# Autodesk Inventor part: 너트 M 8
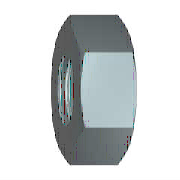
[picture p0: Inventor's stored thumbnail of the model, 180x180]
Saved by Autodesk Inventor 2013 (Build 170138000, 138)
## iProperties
IsCustomPart: 1
Created: 2012-02
Part Number: 너트 M 8
Material: 강철, 연강
Description: 6각 너트 및 6각 가는 너트
Document SubType Name: Modeling
Standard: KS B 1012
Designer: mduedu
Standards Organization: KS
Language: ko-KR
Size Designation: M 8
Categories: <MemberInstance><Categories><Category DisplayName="조임쇠" InternalName="e4da775c-781d-43d5-af7c-5136215cf5a6" Mnemonic="FSTN"><Category DisplayName="너트" InternalN
Density: 1 g/cm^3
Author: mduedu
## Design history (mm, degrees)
sketch "스케치1"
  geometry: L1 (-7.506, 0)-(-3.753, 6.5); L2 (-3.753, 6.5)-(3.753, 6.5); L3 (3.753, 6.5)-(7.506, 0); L4 (7.506, 0)-(3.753, -6.5); L5 (3.753, -6.5)-(-3.753, -6.5); L6 (-3.753, -6.5)-(-7.506, 0); 2 further points
  constraints: 12 end point, 1 coincident, 1 horizontal, 11 other
  dimensions: "d0" = 15.01111 distance of L3.end L1.start (= 1.1547 x SW)
extrude "본체" new body sketch "스케치1" distance "d1" = 5 (= KOH); taper "d2" = 0 deg
sketch "스케치2"
  geometry: L1 (0, 3.753)-(0, 7.506) reference; L2 (0, 7.506)-(5, 7.506) reference; L3 (5, 3.753)-(5, 7.506) reference; L4 (-1, 0)-(6, 0) reference; L5 (0.581, 7.506)-(0, 6.5); L6 (4.419, 7.506)-(5, 6.5)
  constraints: 4 end point, 4 point on line
  dimensions: "d3" = 30 deg angle of L1 L5 (= ANG1); "d4" = 30 deg angle of L3 L6 (= ANG2); "d5" = 13 diameter of L5.end L4 (= SW0); "d6" = 13 diameter of L6.end L4 (= SW01)
revolve "모따기1" sketch "스케치2" stored, may be unused: angle "d7" = 90 deg
sketch "스케치3"
  geometry: A1 r 6.5 centre (0, 0) between (-3.25, -5.629) and (3.25, -5.629) reference; 1 further point
  constraints: 1 coincident
hole "스레드" sketch "스케치3" at (0, 0) diameter "d25" = 6.647; stored, may be unused: countersink angle "d29" = 82 deg, drill point angle "d31" = 118 deg; dims "d26" = 6, "d27" = 4, "d28" = 2, "d30" = 8
workaxis "Work Axis1"
workplane "Work Plane1"
body "Solid1"
chamfer "모따기2" distance "d8" = 0.67658 (= -0.5 x GD1 + 0.5 x NND); stored, may be unused: angle "d9" = 30 deg, second distance "d40" = 0.67658 (= -0.5 x GD1 + 0.5 x NND)
chamfer "모따기3" distance "d10" = 0.67658 (= -0.5 x GD1 + 0.5 x NND); stored, may be unused: angle "d11" = 30 deg, second distance "d41" = 0.67658 (= -0.5 x GD1 + 0.5 x NND)
other parameters: "ANG1" = 30 deg [user parameter; used in 1 equation term], "ANG2" = 30 deg [user parameter; used in 1 equation term], "NND" = 8 [user parameter; used in 4 equation terms], "KOH" = 5 [user parameter; used in 1 equation term], "SW" = 13 [user parameter; used in 4 equation terms], "SW0" = 13 (= SW) [user parameter; used in 1 equation term], "SW01" = 13 (= SW) [user parameter; used in 1 equation term], "GD1" = 6.64684 (computed from THREADDIA, PTC, TOA) [user parameter; used in 4 equation terms], "d13" = 0, "d14" = 0, "d39" = 0, "d42" = 0, "GUL" = 0.67658 (= 0.541266 x PTC) [user parameter], "TPU" = 8 (computed from PTC) [user parameter], "THREADDIA" = 8 [user parameter; used in 1 equation term], "TOA" = 30 deg [user parameter; used in 1 equation term], "PTC" = 1.25 [user parameter; used in 4 equation terms], "E0" = 15.015 (= 1.155 x SW) [user parameter], "GAL" = 0.67658 (= 0.541266 x PTC) [user parameter]
